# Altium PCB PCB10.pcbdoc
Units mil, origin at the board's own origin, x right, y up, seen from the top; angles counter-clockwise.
Board outline 6905 x 1215 mil, 2 copper layers (Top Layer, Bottom Layer); 16 components, 14 nets, 52 pads, 3 vias.
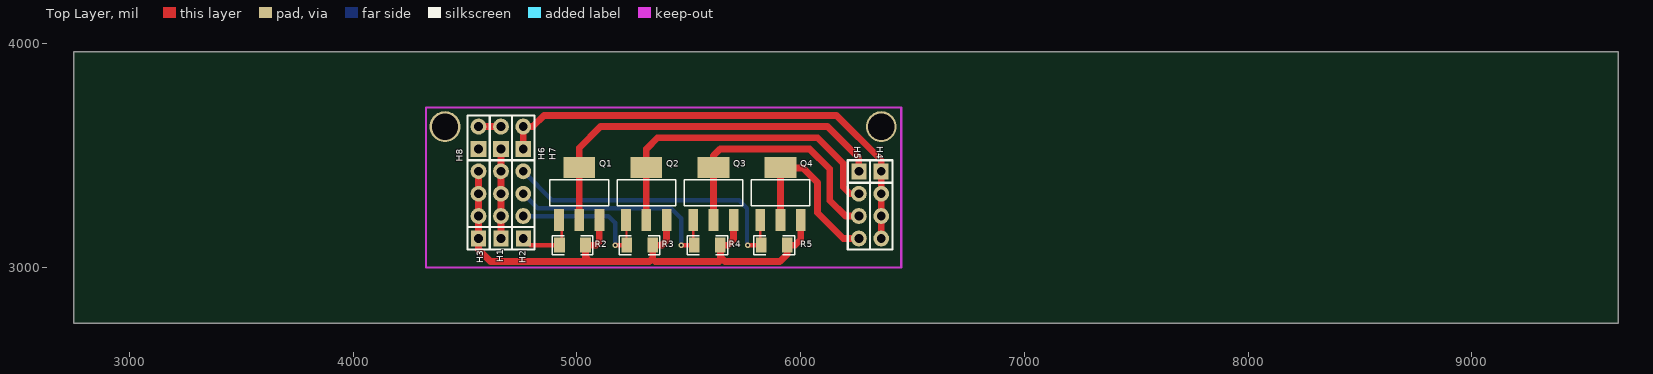
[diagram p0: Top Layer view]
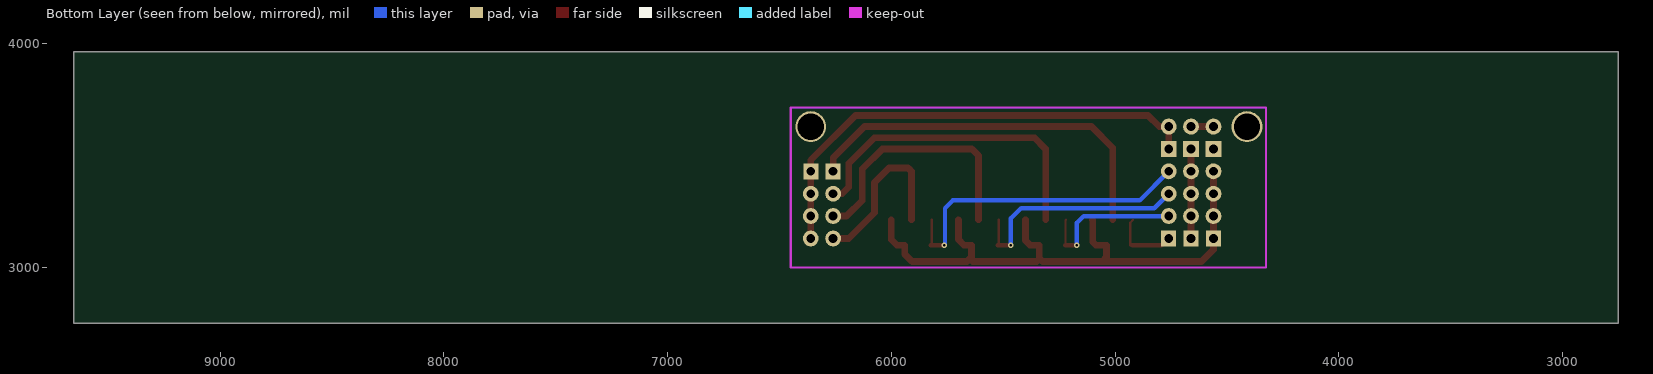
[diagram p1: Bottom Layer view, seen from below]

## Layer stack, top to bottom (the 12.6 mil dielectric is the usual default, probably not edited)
Top Layer: signal copper (thickness not stored)
Dielectric: dielectric 12.6, FR-4, Dk 4.8
Bottom Layer: signal copper (thickness not stored)

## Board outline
9655,2750 2750,2750 2750,3965 9655,3965

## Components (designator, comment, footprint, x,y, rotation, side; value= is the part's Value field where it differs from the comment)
H1 "HDR-M_2.54_1x4P" hdr-th_4p-p2.54-v-m 4660,3280 r90 top
H2 "HDR-M_2.54_1x4P" hdr-th_4p-p2.54-v-m 4760,3280 r90 top
H3 "HDR-M_2.54_1x4P" hdr-th_4p-p2.54-v-m 4560,3280 r90 top
H4 "HDR-M_2.54_1x4P" hdr-th_4p-p2.54-v-m 6360,3280 r270 top
H5 "HDR-M_2.54_1x4P" hdr-th_4p-p2.54-v-m 6260,3280 r270 top
H6 "HDR-M_2.54_1x2P" HDR-TH_2P-P2.54-V-M-1 4660,3580 r90 top
H7 "HDR-M_2.54_1x2P" HDR-TH_2P-P2.54-V-M-1 4760,3580 r90 top
H8 "HDR-M_2.54_1x2P" HDR-TH_2P-P2.54-V-M-1 4560,3580 r90 top
Q1 "BUK98150-55A/CUF" SOT-223-3_L6.5-W3.4-P2.30-LS7.0-BR 5010,3330 r270 top
Q2 "BUK98150-55A/CUF" SOT-223-3_L6.5-W3.4-P2.30-LS7.0-BR 5310,3330 r270 top
Q3 "BUK98150-55A/CUF" SOT-223-3_L6.5-W3.4-P2.30-LS7.0-BR 5610,3330 r270 top
Q4 "BUK98150-55A/CUF" SOT-223-3_L6.5-W3.4-P2.30-LS7.0-BR 5910,3330 r270 top
R2 "1206W4F1002T5E" R1206 4980.11,3099.66 r180 top
R3 "1206W4F1002T5E" R1206 5280,3100 r180 top
R4 "1206W4F1002T5E" R1206 5582.93,3099.66 r180 top
R5 "1206W4F1002T5E" R1206 5882.15,3099.66 r180 top

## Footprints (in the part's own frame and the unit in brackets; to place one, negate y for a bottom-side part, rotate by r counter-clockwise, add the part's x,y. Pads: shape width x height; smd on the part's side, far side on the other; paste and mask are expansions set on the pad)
HDR-TH_2P-P2.54-V-M-1 [mm]
  rect 1.8x1.8 hole 1: 1(-1.27,0)
  round 1.8 hole 1: 2(1.27,0)
  silkscreen extent -2.54,-1.27 2.54,1.27
hdr-th_4p-p2.54-v-m [mm]
  rect 1.801x1.7 hole 1.001: 1(-3.81,0)
  round 1.801 hole 1.001: 2(-1.27,0) 3(1.27,0) 4(3.81,0)
  silkscreen extent -5.08,-1.27 5.08,1.27
R1206 [mil]
  rect 47.54x66.97 smd: 1(-58.22,0) 2(58.22,0)
  silkscreen extent -91,-42 91,42
SOT-223-3_L6.5-W3.4-P2.30-LS7.0-BR [mm]
  rect 2.5x1.1 smd: 1(2.97,-2.3) 2(2.97,0) 3(2.97,2.3)
  rect 2.34x3.6 smd: 4(-2.97,0)
  silkscreen extent -1.57,-3.33 1.37,3.33

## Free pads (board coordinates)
  round 137.8 hole 118.1: 5(4410,3630) 5(6360,3630)

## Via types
v1: diameter 24.02, hole 12.01, Top Layer to Bottom Layer, 3 vias

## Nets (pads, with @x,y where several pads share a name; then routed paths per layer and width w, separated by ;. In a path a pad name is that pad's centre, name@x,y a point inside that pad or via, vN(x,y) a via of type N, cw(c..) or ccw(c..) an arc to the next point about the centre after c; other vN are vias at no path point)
5V: H8.1
CMDLAMP: H2.4 Q4.1 R5.2 | length 1410.9
  Top Layer w10: Q4.1 5819.45,3104.14 R5.2
  Top Layer w20: v1(5763.37,3099.66) R5.2
  Bottom Layer w20: H2.4 4890,3300 5725,3300 5760,3265 5760,3103.03 v1(5763.37,3099.66)
CMDP1: H2.1 Q1.1 R2.2 | length 293
  Top Layer w10: Q1.1 4931.89,3200.63 R2.2@4931.89,3099.66
  Top Layer w20: H2.1 4790.34,3099.66 R2.2
CMDP2: H2.2 Q2.1 R3.2 | length 687.8
  Top Layer w10: Q2.1 5221.78,3210.74 R3.2
  Top Layer w20: v1(5170.78,3100) R3.2
  Bottom Layer w20: H2.2 5140,3230 5170,3200 5170,3100.78 v1(5170.78,3100)
CMDP3: H2.3 Q3.1 R4.2 | length 1045.1
  Top Layer w10: Q3.1 5519.45,3104.92 5524.37,3100 R4.2
  Top Layer w20: v1(5465.76,3100) R4.2@5524.37,3100
  Bottom Layer w20: H2.3 4825,3265 5420,3265 5465,3220 5465,3100.76 v1(5465.76,3100)
GND: H3.1 H3.2 H3.3 H3.4 pad.5 Q1.3 Q2.3 Q3.3 Q4.3 R2.1 R3.1 R4.1 R5.1 | length 2672.9
  Top Layer w30: H3.4 H3.3 H3.2 H3.1 4560,3080 4613.2,3026.8 5044.42,3026.8 ; Q1.3 5100,3212.52 5100,3115 5084.66,3099.66 R2.1 5038.33,3046.08 5044.42,3040 5044.42,3026.8 ; Q2.3 5400.55,3120.55 5380,3100 R3.1 5338.22,3040 5336.76,3040 ; Q3.3 5700,3212.52 5700,3125 5674.66,3099.66 R4.1 5641.15,3047.71 5648.86,3040 ; Q4.3 6000,3212.52 6000,3125 5974.66,3099.66 R5.1 5940.37,3060.37 5906.8,3026.8 5662.06,3026.8 5648.86,3040 ; 5044.42,3026.8 5323.56,3026.8 5336.76,3040 ; 5336.76,3040 5349.96,3026.8 5635.66,3026.8 5648.86,3040
POWERLAMP: H5.4 Q4.2 Q4.4 | length 799.6
  Top Layer w10: Q4.4@5910,3430 Q4.4
  Top Layer w30: Q4.2 5910,3430 5925,3445 6010,3445 6075,3380 6075,3245 6190,3130 H5.4
POWERPUMP1: H5.1 Q1.2 Q1.4 | length 1729.3
  Top Layer w30: Q1.2 Q1.4 5010,3535 5105,3630 6120,3630 6260,3490 H5.1
POWERPUMP2: H5.2 Q2.2 Q2.4 | length 1452.7
  Top Layer w30: Q2.2 Q2.4 5310,3530 5360,3580 6075,3580 6190,3465 6190,3360 6220,3330 H5.2
POWERPUMP3: H5.3 Q3.2 Q3.4 | length 1155.6
  Top Layer w30: Q3.2 Q3.4 5610,3500 5640,3530 6040,3530 6130,3440 6130,3300 6200,3230 H5.3
VBAT: H1.1 H1.2 H1.3 H1.4 H6.1 | length 400
  Top Layer w30: H1.1 H1.2 H1.3 H1.4 H6.1
VEXT: H6.2 H8.2 | length 100
  Top Layer w30: H8.2 H6.2
VIN: H4.1 H4.2 H4.3 H4.4 H7.1 H7.2 | length 2153.6
  Top Layer w30: H7.1 H7.2 4802.43,3630 4852.43,3680 6160,3680 6360,3480 H4.1 H4.2 H4.3 H4.4
"": 

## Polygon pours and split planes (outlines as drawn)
GND on Bottom Layer (solid, remove dead copper, pour order 0): 4325,3000 6450,3000 6450,3715 4325,3715

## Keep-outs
Board Outline Layer:
  lines w10 net "": 4325,3000 6450,3000 6450,3715 4325,3715 4325,3000

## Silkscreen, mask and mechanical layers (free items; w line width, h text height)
Mech6:
  text "5V/ VEXT - VIN JUMPER /  GND/VBAT - VIN JUMPER /  " at 2866.13,3407.2 h72.35
  text "POWERPUMP1/VIN /  POWERPUMP2/VIN /  POWERPUMP3/VIN /  POWERLAMP/VIN" at 6395.16,3102.2 h75.57
  text "GND/VBAT/CMDLAMP /  GND/VBAT/CMDPUMP3 /  GND/VBAT/CMDPUMP2 /  GND/VBAT/CMDPUMP1" at 3065.6,3097.2 h75.57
